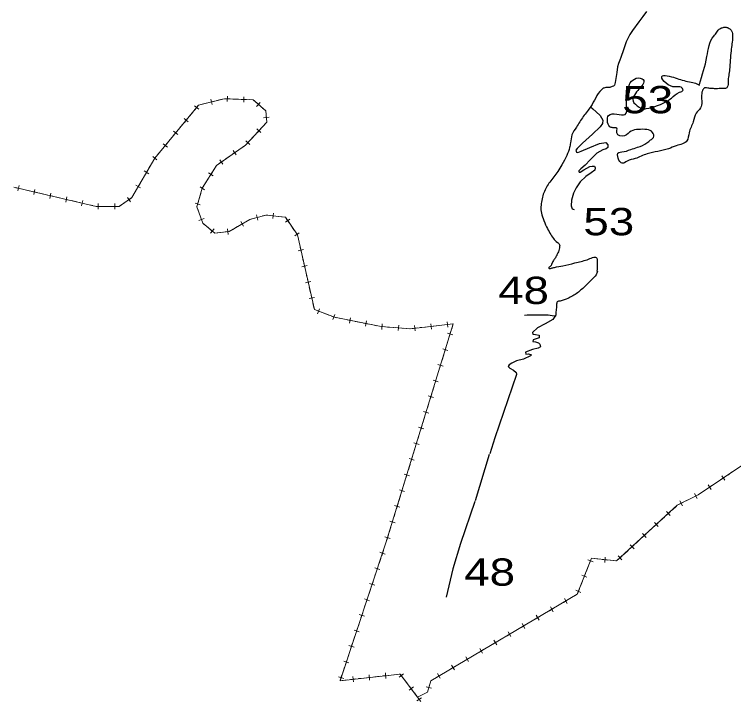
# Model space of a CAD drawing. Extents: x 476989 to 498418, y 4381813 to 4416555.
# Drawn here: x 485527 to 486843, y 4382275 to 4383532 of the extents above; entities that cross this region are included whole.
import ezdxf

# ---------------------------------------------------------------- set-up
doc = ezdxf.new("R2010")
doc.units = 0
doc.header["$LTSCALE"] = 20
for name, color, linetype, lineweight in [('13', 7, 'Continuous', 13), ('34', 7, 'Continuous', 13), ('6', 7, 'Continuous', 25)]:
    doc.layers.add(name, color=color, linetype=linetype, lineweight=lineweight)

msp = doc.modelspace()

# ---------------------------------------------------------------- linework, layer by layer
at = {"layer": '13', "lineweight": 25}
msp.add_spline([(486780.88, 4383404.79), (486794.13, 4383455.03), (486806.75, 4383492.74), (486812.33, 4383499.64), (486814.71, 4383503.51), (486819.41, 4383506.81), (486825.21, 4383508.61), (486829.49, 4383508.62), (486831.66, 4383508.22), (486834.79, 4383506.67), (486839.23, 4383502.48), (486841.25, 4383491.57), (486838.33, 4383465.65), (486835.59, 4383431.7), (486834, 4383420.31), (486833.25, 4383414.77), (486832.97, 4383406.37), (486832.3, 4383401.5), (486829.47, 4383397.12), (486823.83, 4383396.67), (486809.94, 4383396.27), (486802.97, 4383396.6), (486796, 4383397.37), (486791.44, 4383398.19), (486788.79, 4383396.8), (486785.88, 4383392.64), (486784.6, 4383386.95), (486784.53, 4383376.98), (486784.84, 4383372.17), (486782.2, 4383361.03), (486774.71, 4383351.45), (486769.08, 4383335.85), (486761.59, 4383315.77), (486757.7, 4383301.05), (486738.21, 4383291.87), (486723.87, 4383286.22), (486684.72, 4383277.1), (486662.99, 4383268.56), (486648.14, 4383263.67), (486639.3, 4383259.75), (486632.91, 4383279.8), (486638.33, 4383280.62), (486654.82, 4383284.96), (486667.34, 4383289.06), (486684.49, 4383297.14), (486691.09, 4383302.53), (486696.41, 4383307.18), (486694.82, 4383316.43), (486684.24, 4383321.46), (486669.01, 4383321.68), (486655.38, 4383318.57), (486643.48, 4383310.34), (486629.22, 4383315.27), (486629.5, 4383324.04), (486622.3, 4383324.82), (486616.85, 4383326.7), (486612.21, 4383337.87), (486614.37, 4383347.45), (486644.42, 4383349.27), (486649.2, 4383384.92), (486651.66, 4383388.63), (486652.89, 4383395.9), (486652.14, 4383401.38), (486671.78, 4383415.81), (486678.55, 4383411.44), (486675.33, 4383401.28), (486669.84, 4383395.35), (486659.1, 4383373.67), (486670.12, 4383362.71), (486675.25, 4383359.48), (486683.36, 4383359.82), (486702.12, 4383364.88), (486729.49, 4383379.19), (486744.12, 4383389.71), (486750.48, 4383393.52), (486749.77, 4383396.53), (486731.96, 4383399.94), (486712.51, 4383419.8), (486725.33, 4383419.24), (486752.3, 4383411.05), (486765.39, 4383408.24), (486770.85, 4383407.04), (486780.7, 4383403.07)], degree=3, dxfattribs=at)
at = {"layer": '34'}
for p, q in [((485882.86, 4383370.82), (485892.55, 4383373.29)), ((485886.47, 4383376.9), (485888.94, 4383367.21)), ((485897.4, 4383374.53), (485907.09, 4383377)), ((485911.95, 4383377.96), (485921.94, 4383377.59)), ((485917.13, 4383382.77), (485916.76, 4383372.78)), ((485926.94, 4383377.4), (485936.93, 4383377.02)), ((485941.92, 4383376.83), (485951.91, 4383376.46)), ((485947.1, 4383381.64), (485946.73, 4383371.65)), ((485856.63, 4383364.92), (485864.34, 4383358.56)), ((485857.31, 4383357.88), (485863.67, 4383365.6)), ((485868.34, 4383367.11), (485878.03, 4383369.58)), ((485969.96, 4383370.82), (485977.5, 4383364.26)), ((485977.01, 4383371.31), (485970.45, 4383363.77)), ((485847.77, 4383346.32), (485854.13, 4383354.03)), ((485987.7, 4383348.63), (485988.65, 4383338.68)), ((485837.55, 4383341.78), (485845.26, 4383335.42)), ((485838.22, 4383334.75), (485844.59, 4383342.46)), ((485988.11, 4383334.04), (485981.31, 4383326.71)), ((485993.15, 4383344.13), (485983.2, 4383343.18)), ((485828.69, 4383323.18), (485835.05, 4383330.9)), ((485978.17, 4383315.99), (485970.84, 4383322.8)), ((485977.91, 4383323.06), (485971.11, 4383315.73)), ((485809.6, 4383300.05), (485815.97, 4383307.76)), ((485818.47, 4383318.65), (485826.18, 4383312.29)), ((485819.14, 4383311.61), (485825.5, 4383319.32)), ((485967.7, 4383312.07), (485960.9, 4383304.74)), ((485799.38, 4383295.51), (485807.1, 4383289.15)), ((485800.06, 4383288.47), (485806.42, 4383296.19)), ((485957.76, 4383294.01), (485950.44, 4383300.82)), ((485957.5, 4383301.08), (485950.7, 4383293.75)), ((485790.52, 4383276.91), (485796.89, 4383284.62)), ((485934.45, 4383282.15), (485926.25, 4383276.42)), ((485933.21, 4383275.18), (485927.49, 4383283.38)), ((485946.74, 4383290.73), (485938.54, 4383285)), ((485780.3, 4383272.38), (485788.02, 4383266.01)), ((485922.15, 4383273.56), (485913.95, 4383267.83)), ((485774.05, 4383251.95), (485779.09, 4383260.59)), ((485909.86, 4383264.98), (485901.66, 4383259.25)), ((485908.62, 4383258.02), (485902.9, 4383266.22)), ((485764.7, 4383245.83), (485773.33, 4383240.79)), ((485766.5, 4383238.99), (485771.54, 4383247.63)), ((485891.09, 4383236.95), (485882.59, 4383242.22)), ((485889.47, 4383243.84), (485884.21, 4383235.33)), ((485758.94, 4383226.05), (485763.98, 4383234.68)), ((485881.57, 4383231.08), (485876.31, 4383222.58)), ((485529.63, 4383215.16), (485539.37, 4383212.9)), ((485535.63, 4383218.9), (485533.37, 4383209.16)), ((485749.59, 4383219.93), (485758.22, 4383214.89)), ((485751.39, 4383213.09), (485756.42, 4383221.73)), ((485875.3, 4383211.45), (485866.8, 4383216.72)), ((485544.24, 4383211.77), (485553.99, 4383209.51)), ((485558.85, 4383208.39), (485568.59, 4383206.13)), ((485564.85, 4383212.13), (485562.59, 4383202.39)), ((485573.46, 4383205), (485583.2, 4383202.74)), ((485588.06, 4383201.61), (485597.8, 4383199.36)), ((485594.06, 4383205.36), (485591.8, 4383195.61)), ((485743.83, 4383200.14), (485748.87, 4383208.78)), ((485868.21, 4383204.5), (485865.39, 4383194.91)), ((485602.67, 4383198.23), (485612.42, 4383195.97)), ((485617.28, 4383194.84), (485627.02, 4383192.58)), ((485623.28, 4383198.58), (485621.02, 4383188.84)), ((485631.89, 4383191.46), (485641.63, 4383189.2)), ((485652.49, 4383191.81), (485650.23, 4383182.07)), ((485732.67, 4383190.51), (485740.88, 4383196.22)), ((485733.92, 4383197.47), (485739.63, 4383189.26)), ((485863.98, 4383190.12), (485861.16, 4383180.53)), ((485646.49, 4383188.07), (485656.23, 4383185.81)), ((485661.11, 4383184.68), (485670.85, 4383182.43)), ((485680.67, 4383186), (485680.67, 4383176)), ((485690.67, 4383181), (485700.67, 4383181)), ((485705.66, 4383181), (485715.66, 4383181)), ((485710.66, 4383186), (485710.66, 4383176)), ((485720.37, 4383181.95), (485728.58, 4383187.66)), ((485867.36, 4383183.91), (485857.77, 4383186.74)), ((485862.53, 4383175.82), (485865.97, 4383166.43)), ((485966.62, 4383159.38), (485976.26, 4383162.04)), ((485970.11, 4383165.53), (485972.77, 4383155.89)), ((485995.79, 4383164.02), (486005.73, 4383162.92)), ((486001.31, 4383168.44), (486000.21, 4383158.5)), ((486010.7, 4383162.37), (486020.64, 4383161.26)), ((485874.11, 4383158.78), (485864.72, 4383155.33)), ((485867.69, 4383161.75), (485871.13, 4383152.36)), ((485939.78, 4383146.45), (485948.44, 4383151.46)), ((485941.6, 4383153.29), (485946.61, 4383144.63)), ((486031.43, 4383157.56), (486023.19, 4383151.89)), ((486024.48, 4383158.85), (486030.15, 4383150.61)), ((485873.92, 4383148.43), (485881.66, 4383142.09)), ((485885.53, 4383138.93), (485893.27, 4383132.6)), ((485892.56, 4383139.64), (485886.23, 4383131.9)), ((485917.31, 4383139.72), (485918.46, 4383129.79)), ((485926.81, 4383138.94), (485935.46, 4383143.95)), ((486032.98, 4383146.48), (486038.64, 4383138.24)), ((485898.02, 4383132.46), (485907.96, 4383133.61)), ((486048.42, 4383132.84), (486040.18, 4383127.18)), ((486046.94, 4383120.44), (486049.14, 4383110.69)), ((486056.22, 4383102.05), (486046.47, 4383099.84)), ((486050.24, 4383105.82), (486052.45, 4383096.07)), ((486053.55, 4383091.19), (486055.76, 4383081.44)), ((486062.84, 4383072.8), (486053.09, 4383070.59)), ((486056.86, 4383076.57), (486059.07, 4383066.82)), ((486060.17, 4383061.94), (486062.38, 4383052.19)), ((486069.46, 4383043.55), (486059.71, 4383041.34)), ((486063.48, 4383047.32), (486065.69, 4383037.57)), ((486066.79, 4383032.69), (486069, 4383022.94)), ((486070.1, 4383018.07), (486072.31, 4383008.32)), ((486076.08, 4383014.3), (486066.33, 4383012.09)), ((486073.41, 4383003.44), (486075.62, 4382993.69)), ((486085.49, 4382993.75), (486081.95, 4382984.4)), ((486079.05, 4382990.85), (486088.4, 4382987.31)), ((486093.08, 4382985.54), (486102.43, 4382982)), ((486113.54, 4382983.14), (486110, 4382973.79)), ((486121.52, 4382976.3), (486131.32, 4382974.34)), ((486136.22, 4382973.36), (486146.02, 4382971.4)), ((486142.1, 4382977.28), (486140.14, 4382967.47)), ((486150.93, 4382970.41), (486160.73, 4382968.45)), ((486165.63, 4382967.47), (486175.43, 4382965.51)), ((486171.51, 4382971.4), (486169.55, 4382961.59)), ((486200.34, 4382965.84), (486199.6, 4382955.87)), ((486288.97, 4382966.3), (486290.12, 4382956.37)), ((486314.37, 4382964.2), (486324.31, 4382965.34)), ((486318.77, 4382969.74), (486319.91, 4382959.8)), ((486180.33, 4382964.53), (486190.14, 4382962.57)), ((486209.94, 4382960.12), (486219.91, 4382959.38)), ((486224.89, 4382959.01), (486234.86, 4382958.27)), ((486230.25, 4382963.63), (486229.51, 4382953.65)), ((486239.85, 4382957.9), (486249.82, 4382957.16)), ((486254.79, 4382957.32), (486264.72, 4382958.47)), ((486259.18, 4382962.86), (486260.33, 4382952.93)), ((486269.69, 4382959.04), (486279.62, 4382960.19)), ((486284.58, 4382960.76), (486294.51, 4382961.91)), ((486299.48, 4382962.48), (486309.42, 4382963.62)), ((486325.82, 4382952.37), (486322.89, 4382942.81)), ((486329.13, 4382946.12), (486319.57, 4382949.05)), ((486321.42, 4382938.03), (486318.49, 4382928.47)), ((486320.34, 4382917.45), (486310.78, 4382920.38)), ((486317.02, 4382923.7), (486314.09, 4382914.14)), ((486312.63, 4382909.36), (486309.69, 4382899.8)), ((486311.54, 4382888.78), (486301.98, 4382891.71)), ((486308.23, 4382895.02), (486305.3, 4382885.46)), ((486303.83, 4382880.68), (486300.9, 4382871.12)), ((486302.75, 4382860.11), (486293.19, 4382863.04)), ((486299.44, 4382866.35), (486296.5, 4382856.79)), ((486295.04, 4382852.01), (486292.1, 4382842.45)), ((486293.95, 4382831.44), (486284.39, 4382834.37)), ((486290.64, 4382837.68), (486287.71, 4382828.12)), ((486286.24, 4382823.34), (486283.31, 4382813.78)), ((486281.85, 4382809.01), (486278.91, 4382799.45)), ((486277.45, 4382794.67), (486274.51, 4382785.11)), ((486285.16, 4382802.76), (486275.6, 4382805.7)), ((486276.37, 4382774.09), (486266.81, 4382777.02)), ((486273.05, 4382780.34), (486270.12, 4382770.78)), ((486268.65, 4382766), (486265.72, 4382756.44)), ((486267.57, 4382745.42), (486258.01, 4382748.35)), ((486264.26, 4382751.67), (486261.32, 4382742.11)), ((486259.86, 4382737.33), (486256.93, 4382727.77)), ((486258.78, 4382716.75), (486249.22, 4382719.68)), ((486255.46, 4382723), (486252.53, 4382713.44)), ((486251.06, 4382708.65), (486248.13, 4382699.09)), ((486249.98, 4382688.08), (486240.42, 4382691.01)), ((486246.67, 4382694.32), (486243.74, 4382684.76)), ((486840.6, 4382694.9), (486832.29, 4382689.34)), ((486242.27, 4382679.98), (486239.34, 4382670.42)), ((486815.67, 4382678.22), (486807.36, 4382672.66)), ((486828.14, 4382686.56), (486819.83, 4382681)), ((486826.77, 4382679.63), (486821.2, 4382687.94)), ((486241.19, 4382659.41), (486231.63, 4382662.34)), ((486237.87, 4382665.65), (486234.94, 4382656.09)), ((486803.22, 4382669.88), (486794.91, 4382664.32)), ((486801.84, 4382662.94), (486796.28, 4382671.25)), ((486233.47, 4382651.31), (486230.54, 4382641.75)), ((486776.08, 4382646.45), (486771.61, 4382655.4)), ((486790.75, 4382661.54), (486782.44, 4382655.97)), ((486229.08, 4382636.98), (486226.15, 4382627.42)), ((486751.49, 4382639.75), (486742.55, 4382635.28)), ((486749.26, 4382633.04), (486744.79, 4382641.98)), ((486764.9, 4382646.45), (486755.96, 4382641.98)), ((486224.68, 4382622.64), (486221.75, 4382613.08)), ((486232.39, 4382630.73), (486222.83, 4382633.67)), ((486727.08, 4382615.34), (486720.32, 4382622.7)), ((486738.42, 4382632.55), (486731.05, 4382625.78)), ((486716.34, 4382612.25), (486708.97, 4382605.49)), ((486727.38, 4382622.4), (486720.02, 4382615.64)), ((486223.6, 4382602.06), (486214.04, 4382605)), ((486220.28, 4382608.31), (486217.35, 4382598.75)), ((486705.3, 4382602.11), (486697.93, 4382595.35)), ((486705, 4382595.05), (486698.23, 4382602.41)), ((486215.89, 4382593.97), (486212.95, 4382584.41)), ((486694.25, 4382591.96), (486686.89, 4382585.2)), ((486214.8, 4382573.39), (486205.24, 4382576.32)), ((486211.49, 4382579.64), (486208.56, 4382570.08)), ((486672.17, 4382571.67), (486664.81, 4382564.9)), ((486683.22, 4382581.82), (486675.85, 4382575.05)), ((486682.92, 4382574.76), (486676.15, 4382582.12)), ((486661.13, 4382561.53), (486653.77, 4382554.76)), ((486660.83, 4382554.46), (486654.07, 4382561.83)), ((486205.52, 4382544.75), (486196.03, 4382547.91)), ((486202.36, 4382551.07), (486199.2, 4382541.59)), ((486650.09, 4382551.38), (486642.73, 4382544.61)), ((486197.61, 4382536.84), (486194.45, 4382527.36)), ((486585.8, 4382530.46), (486576.49, 4382534.13)), ((486582.98, 4382536.94), (486579.31, 4382527.64)), ((486597.84, 4382535.39), (486587.9, 4382536.47)), ((486612.76, 4382533.77), (486602.81, 4382534.85)), ((486607.24, 4382529.34), (486608.33, 4382539.28)), ((486627.66, 4382532.15), (486617.72, 4382533.23)), ((486639.05, 4382541.24), (486631.69, 4382534.47)), ((486638.75, 4382534.17), (486631.99, 4382541.53)), ((486196.04, 4382516.3), (486186.55, 4382519.46)), ((486192.87, 4382522.62), (486189.71, 4382513.14)), ((486577.48, 4382522.99), (486573.82, 4382513.68)), ((486188.13, 4382508.39), (486184.97, 4382498.91)), ((486574.81, 4382502.56), (486565.5, 4382506.22)), ((486571.99, 4382509.04), (486568.32, 4382499.74)), ((486186.55, 4382487.85), (486177.07, 4382491.01)), ((486183.39, 4382494.17), (486180.23, 4382484.69)), ((486566.49, 4382495.09), (486562.82, 4382485.78)), ((486178.65, 4382479.94), (486175.49, 4382470.46)), ((486563.81, 4382474.65), (486554.51, 4382478.32)), ((486560.99, 4382481.14), (486557.33, 4382471.83)), ((486173.91, 4382465.72), (486170.74, 4382456.23)), ((486553.47, 4382468.92), (486544.85, 4382463.84)), ((486169.16, 4382451.49), (486166, 4382442)), ((486177.07, 4382459.4), (486167.58, 4382462.56)), ((486527.63, 4382453.69), (486519.02, 4382448.61)), ((486540.55, 4382461.3), (486531.94, 4382456.22)), ((486538.79, 4382454.46), (486533.71, 4382463.07)), ((486501.8, 4382438.45), (486493.18, 4382433.38)), ((486514.72, 4382446.07), (486506.1, 4382440.99)), ((486512.95, 4382439.23), (486507.87, 4382447.84)), ((486167.59, 4382430.95), (486158.1, 4382434.11)), ((486164.42, 4382437.27), (486161.26, 4382427.78)), ((486488.88, 4382430.84), (486480.27, 4382425.76)), ((486487.12, 4382424), (486482.04, 4382432.61)), ((486159.68, 4382423.04), (486156.52, 4382413.55)), ((486463.05, 4382415.61), (486454.43, 4382410.53)), ((486461.28, 4382408.76), (486456.2, 4382417.38)), ((486475.96, 4382423.22), (486467.35, 4382418.15)), ((486158.1, 4382402.49), (486148.62, 4382405.66)), ((486154.94, 4382408.82), (486151.78, 4382399.33)), ((486437.21, 4382400.38), (486428.6, 4382395.3)), ((486435.45, 4382393.53), (486430.37, 4382402.15)), ((486450.13, 4382407.99), (486441.51, 4382402.91)), ((486150.2, 4382394.59), (486147.03, 4382385.1)), ((486409.61, 4382378.3), (486404.53, 4382386.92)), ((486424.29, 4382392.76), (486415.68, 4382387.68)), ((486148.62, 4382374.04), (486139.13, 4382377.21)), ((486145.46, 4382380.37), (486142.29, 4382370.88)), ((486398.46, 4382377.53), (486389.84, 4382372.45)), ((486411.38, 4382385.15), (486402.77, 4382380.07)), ((486140.71, 4382366.14), (486137.55, 4382356.65)), ((486372.62, 4382362.3), (486364.01, 4382357.22)), ((486385.55, 4382369.92), (486376.93, 4382364.84)), ((486383.78, 4382363.07), (486378.7, 4382371.69)), ((486139.13, 4382345.59), (486129.65, 4382348.75)), ((486135.97, 4382351.92), (486132.81, 4382342.43)), ((486346.79, 4382347.07), (486338.18, 4382341.99)), ((486359.71, 4382354.69), (486351.1, 4382349.61)), ((486357.94, 4382347.84), (486352.86, 4382356.46)), ((486131.23, 4382337.69), (486128.07, 4382328.2)), ((486333.88, 4382339.46), (486325.26, 4382334.38)), ((486332.11, 4382332.61), (486327.03, 4382341.23)), ((486129.65, 4382317.14), (486120.16, 4382320.3)), ((486126.49, 4382323.47), (486123.33, 4382313.98)), ((486146.27, 4382320.57), (486147.36, 4382310.63)), ((486176.09, 4382323.82), (486177.17, 4382313.88)), ((486186.57, 4382319.93), (486196.51, 4382321.02)), ((486201.47, 4382321.56), (486211.41, 4382322.65)), ((486205.9, 4382327.07), (486206.98, 4382317.13)), ((486216.38, 4382323.19), (486226.32, 4382324.27)), ((486238.96, 4382325.43), (486231.01, 4382319.36)), ((486308.04, 4382324.23), (486299.43, 4382319.15)), ((486306.27, 4382317.38), (486301.2, 4382325.99)), ((486320.96, 4382331.84), (486312.34, 4382326.76)), ((486126.94, 4382313.43), (486136.89, 4382314.51)), ((486141.85, 4382315.06), (486151.79, 4382316.14)), ((486156.76, 4382316.68), (486166.7, 4382317.77)), ((486171.66, 4382318.31), (486181.6, 4382319.39)), ((486241.05, 4382314.44), (486247.11, 4382306.49)), ((486257.14, 4382301.57), (486249.18, 4382295.51)), ((486250.13, 4382302.52), (486256.19, 4382294.56)), ((486290.27, 4382299.24), (486280.65, 4382301.98)), ((486286.83, 4382305.42), (486284.09, 4382295.8)), ((486259.22, 4382290.59), (486265, 4382283)), ((486271.92, 4382281.59), (486263.58, 4382276.08)), ((486268.66, 4382284.83), (486265, 4382283)), ((486265, 4382283), (486270.51, 4382274.66)), ((486282.07, 4382291.53), (486273.12, 4382287.06))]:
    msp.add_line(p, q, dxfattribs=at)
for points in [[(485526, 4383216), (485677, 4383181), (485719, 4383181), (485742, 4383197), (485784, 4383269), (485864, 4383366), (485911, 4383378), (485964, 4383376), (485987, 4383356), (485989, 4383335), (485950, 4383293), (485897, 4383256), (485871, 4383214), (485861, 4383180), (485872, 4383150), (485894, 4383132), (485920, 4383135), (485958, 4383157), (485987, 4383165), (486023, 4383161), (486045, 4383129), (486076, 4382992), (486113, 4382978), (486198, 4382961), (486252, 4382957), (486330, 4382966), (486207, 4382565), (486123, 4382313), (486233, 4382325), (486265, 4382283)], [(485956.91, 4383376.27), (485964, 4383376), (485966.19, 4383374.1)], [(485981.27, 4383360.98), (485987, 4383356), (485987.23, 4383353.6)], [(487676.62, 4383311.4), (487577, 4383232), (487304, 4383028), (487077, 4382869), (487054, 4382844), (487031, 4382851), (487023, 4382817), (486778, 4382653), (486740, 4382634), (486629, 4382532), (486583, 4382537), (486557, 4382471), (486289, 4382313), (486283, 4382292), (486265, 4382283)], [(485781.61, 4383264.9), (485784, 4383269), (485787.34, 4383273.05)], [(485897.56, 4383256.39), (485897, 4383256), (485892.1, 4383248.08)], [(485873.68, 4383218.34), (485871, 4383214), (485869.62, 4383209.3)], [(485675.71, 4383181.3), (485677, 4383181), (485685.67, 4383181)], [(485981.08, 4383163.37), (485987, 4383165), (485990.83, 4383164.57)], [(485952.76, 4383153.97), (485958, 4383157), (485961.81, 4383158.05)], [(485912.92, 4383134.18), (485920, 4383135), (485922.48, 4383136.44)], [(486041.47, 4383134.13), (486045, 4383129), (486045.83, 4383125.32)], [(486107.1, 4382980.23), (486113, 4382978), (486116.62, 4382977.28)], [(486329.27, 4382965.92), (486330, 4382966), (486327.28, 4382957.14)], [(486195.03, 4382961.59), (486198, 4382961), (486204.96, 4382960.48)], [(486778.3, 4382653.2), (486778, 4382653), (486769.37, 4382648.69)], [(486207.09, 4382565.3), (486207, 4382565), (486203.94, 4382555.81)], [(486231.29, 4382324.81), (486233, 4382325), (486238.02, 4382318.42)], [(486295.12, 4382316.61), (486289, 4382313), (486288.2, 4382310.22)]]:
    msp.add_lwpolyline(points, dxfattribs=at)
at = {"layer": '6'}
msp.add_line((486396.11, 4382727.09), (486370.16, 4382642.32), dxfattribs=at)
for points in [[(486683.85, 4383537.38), (486677.07, 4383528.72), (486669.63, 4383518.52), (486658.36, 4383502.75), (486653.4, 4383495.54), (486650.12, 4383489.18), (486646.74, 4383482.31), (486641.62, 4383467.51), (486636.62, 4383453.34), (486634.83, 4383448.37), (486632.39, 4383442.5), (486630.76, 4383436.09), (486629.41, 4383425.92), (486627.6, 4383415.24), (486626.45, 4383407.65), (486625.31, 4383403), (486623.23, 4383401.09), (486621.01, 4383400.11), (486616.4, 4383398.76)], [(486581.36, 4383363.04), (486585.6, 4383359.47), (486591.33, 4383354.08), (486598.77, 4383347.36), (486603.73, 4383338.47), (486602.89, 4383332.66), (486599.1, 4383326.49), (486584.93, 4383313.02), (486566.33, 4383296.79), (486556.72, 4383287.17), (486554.58, 4383284.05), (486554.88, 4383281.74), (486555.64, 4383280.33), (486557.96, 4383279.81), (486563.98, 4383281.74), (486580.17, 4383288.52), (486597.42, 4383296.04), (486609.35, 4383297.86), (486612.87, 4383293.86), (486613.06, 4383288.93), (486609.6, 4383286.5), (486603.52, 4383284.14), (486593.03, 4383278.36), (486580.51, 4383266.34), (486571.33, 4383256.67), (486563.64, 4383249.94), (486559.74, 4383245.96), (486559.63, 4383245.23), (486560.47, 4383243.73), (486562.47, 4383243.55), (486569.19, 4383247.72), (486579.91, 4383253.86), (486584.04, 4383254.81), (486588.35, 4383254.3), (486589.81, 4383251.21), (486589.41, 4383247.2), (486582.25, 4383242.17), (486572.68, 4383235.58), (486562.22, 4383225.85), (486555.2, 4383214.86), (486549.89, 4383205.03), (486546.16, 4383192.21), (486545.59, 4383181.98), (486547.39, 4383176.69), (486551.61, 4383175.26)], [(486517.39, 4382981.15), (486512.54, 4382973.9), (486498.53, 4382965.91), (486484.52, 4382958.57), (486475.19, 4382949.91), (486475.85, 4382947.24), (486480.52, 4382946.58), (486487.19, 4382945.24), (486487.19, 4382940.58), (486476.52, 4382936.58), (486475.85, 4382933.91), (486480.52, 4382933.24), (486485.86, 4382931.24), (486488.53, 4382928.58), (486489.86, 4382923.91), (486485.19, 4382921.25), (486475.19, 4382919.25), (486462.51, 4382913.91), (486463.18, 4382910.58), (486467.85, 4382911.25), (486473.18, 4382909.25), (486471.18, 4382907.25), (486458.51, 4382901.25), (486445.84, 4382898.58), (486437.16, 4382893.92), (486432.49, 4382891.25), (486430.49, 4382887.92), (486433.83, 4382884.59), (486440.5, 4382881.25), (486445.17, 4382877.25), (486445.84, 4382873.92)], [(486517.24, 4382979.78), (486511.21, 4382980.64), (486503.53, 4382981.64), (486492.53, 4382981.64), (486482.86, 4382981.97), (486465.18, 4382981.64), (486460.51, 4382981.31)], [(486445.81, 4382873.41), (486406.24, 4382757.15), (486396.79, 4382728.38)], [(486369.4, 4382640.61), (486343.6, 4382563.91), (486329.34, 4382517.49), (486317.11, 4382465.75)]]:
    msp.add_lwpolyline(points, dxfattribs=at)
for points in [[(486616.4, 4383398.76), (486609.53, 4383398.32), (486605.76, 4383397.51), (486603.64, 4383396.68), (486601.06, 4383394.53), (486581.77, 4383363.75), (486567.92, 4383345.34), (486555.49, 4383325.84), (486547.31, 4383311.93), (486544.63, 4383297.26), (486542.93, 4383288.69), (486537.77, 4383273.81), (486528.83, 4383256.87), (486521.61, 4383244.78), (486506.85, 4383225.48), (486495.82, 4383205.81), (486490.76, 4383183.12), (486490.75, 4383171.7), (486494.48, 4383158.89), (486500.87, 4383143.53), (486507.02, 4383132), (486513.34, 4383122.31), (486520.6, 4383114.98), (486524.69, 4383110.49), (486524.72, 4383107.37), (486523.98, 4383102.8), (486520.48, 4383093.44), (486518.01, 4383088.42), (486514.34, 4383083.16), (486511.09, 4383077.17), (486509.02, 4383072.98), (486506.76, 4383070.57), (486504.86, 4383068.89), (486504.98, 4383068.05), (486506.45, 4383067.29), (486509.87, 4383067.88), (486515.23, 4383069.39), (486530.79, 4383072.38), (486552.79, 4383077.34), (486574.89, 4383083.42), (486585.15, 4383087.17), (486588.99, 4383088.06), (486590.1, 4383087.94), (486592.93, 4383085.95), (486593.37, 4383080.97), (486593.38, 4383076.71), (486593.42, 4383068.62), (486592.95, 4383062.34)], [(486593.85, 4383062.23), (486591.36, 4383055.96), (486583.58, 4383046.92), (486572.39, 4383036.05), (486557.19, 4383022.53), (486539.86, 4383012.5), (486525.54, 4383007.75), (486520.42, 4383006.25), (486519.2, 4383000.04), (486518.39, 4382990.6), (486517.24, 4382979.78)]]:
    msp.add_spline(points, degree=3, dxfattribs=at)

# ---------------------------------------------------------------- texts
at = {"layer": '13', "width": 1.25}
for s, p in [('53', (486639.46, 4383351.34)), ('53', (486568.21, 4383128.07)), ('48', (486412.2, 4383002.28)), ('48', (486350.15, 4382486.73))]:
    msp.add_text(s, height=50, dxfattribs=at).set_placement(p)

doc.saveas('drawing.dxf')
